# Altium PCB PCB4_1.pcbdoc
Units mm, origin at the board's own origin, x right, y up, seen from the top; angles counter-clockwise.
Board outline 59.69 x 53.72 mm, 2 copper layers (Top Layer, Bottom Layer); 67 components, 68 nets, 256 pads, 103 vias.
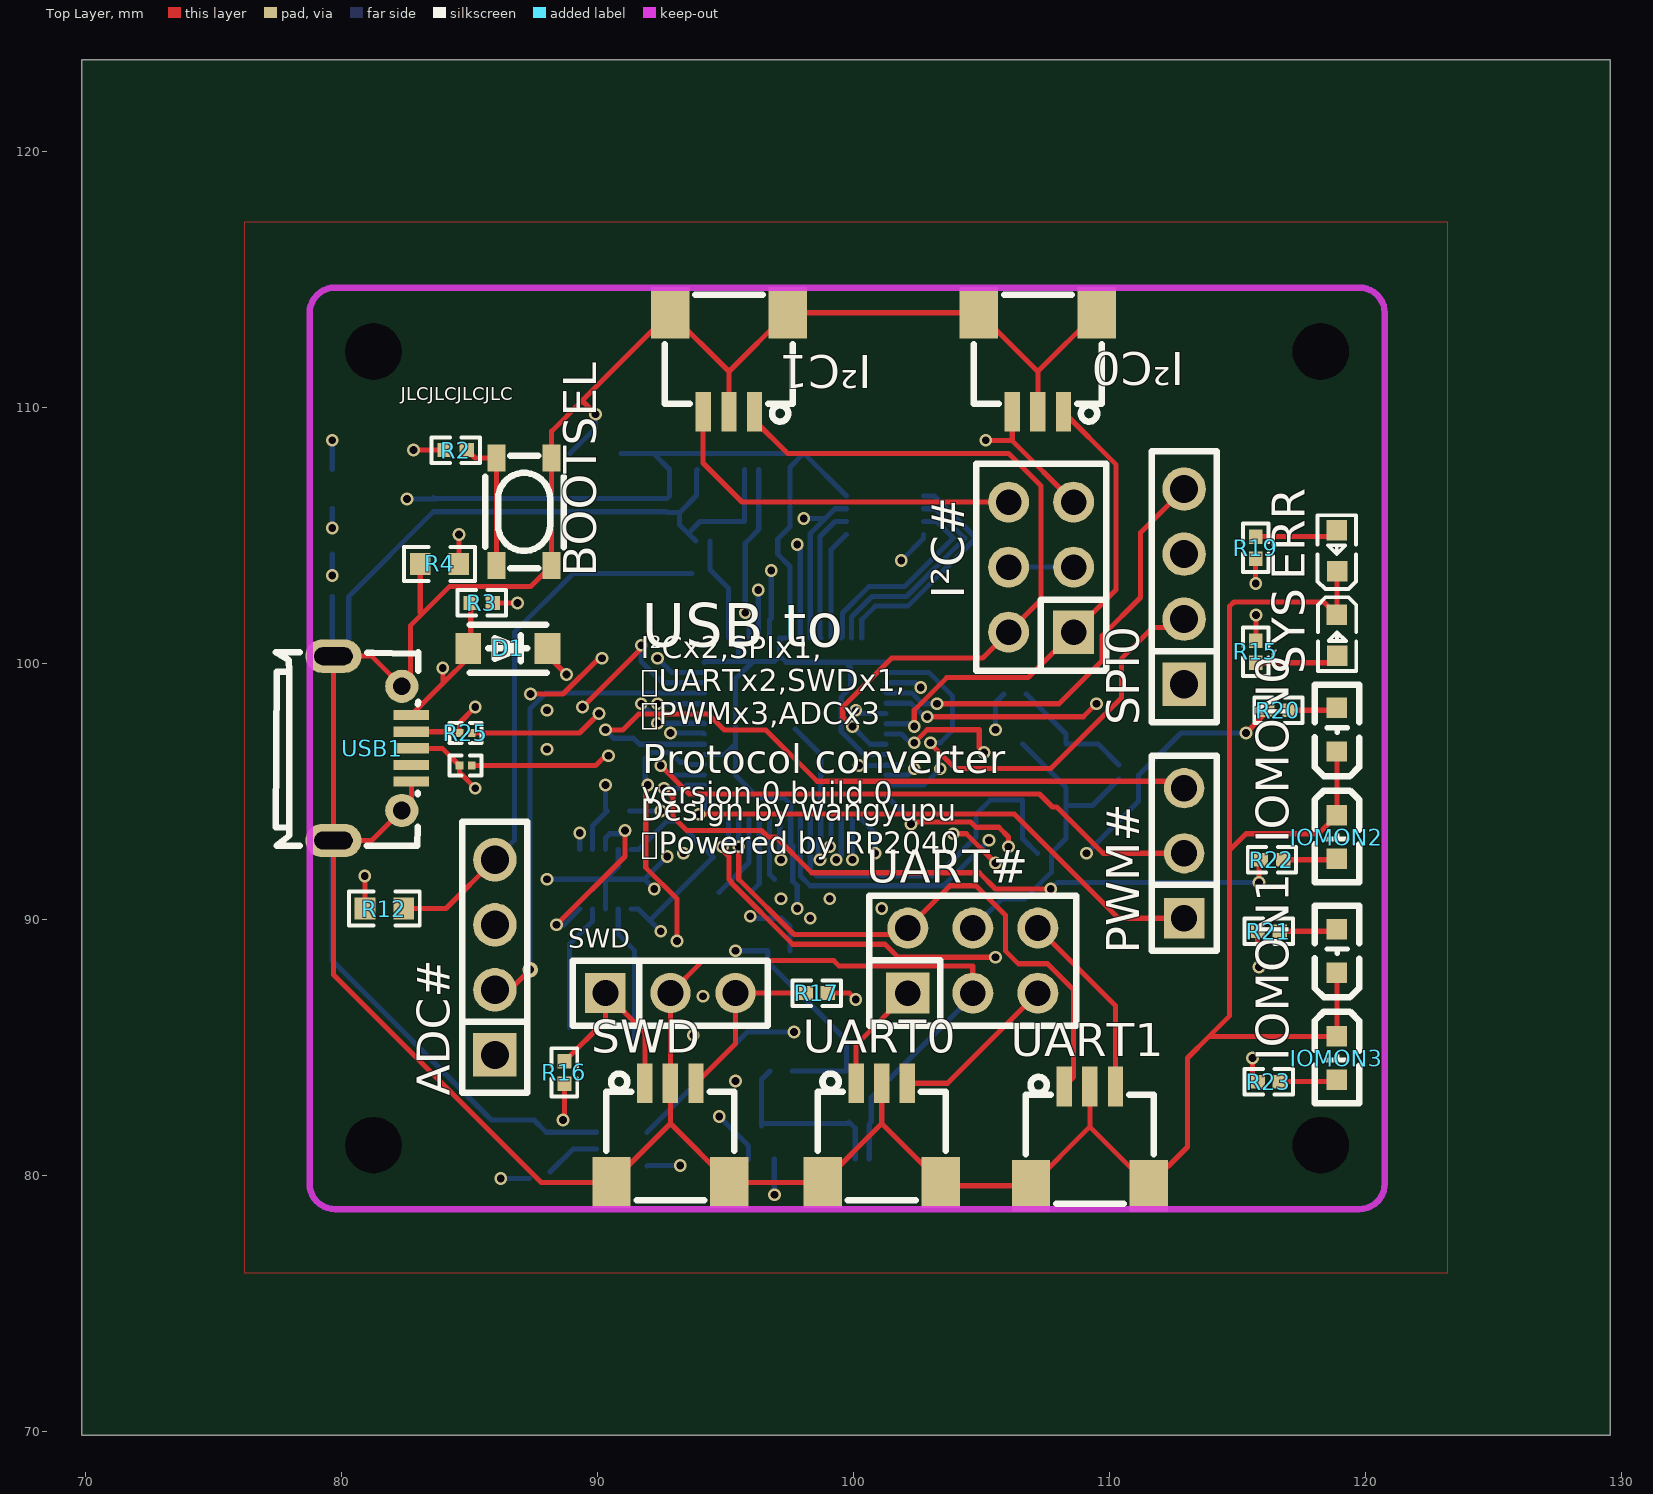
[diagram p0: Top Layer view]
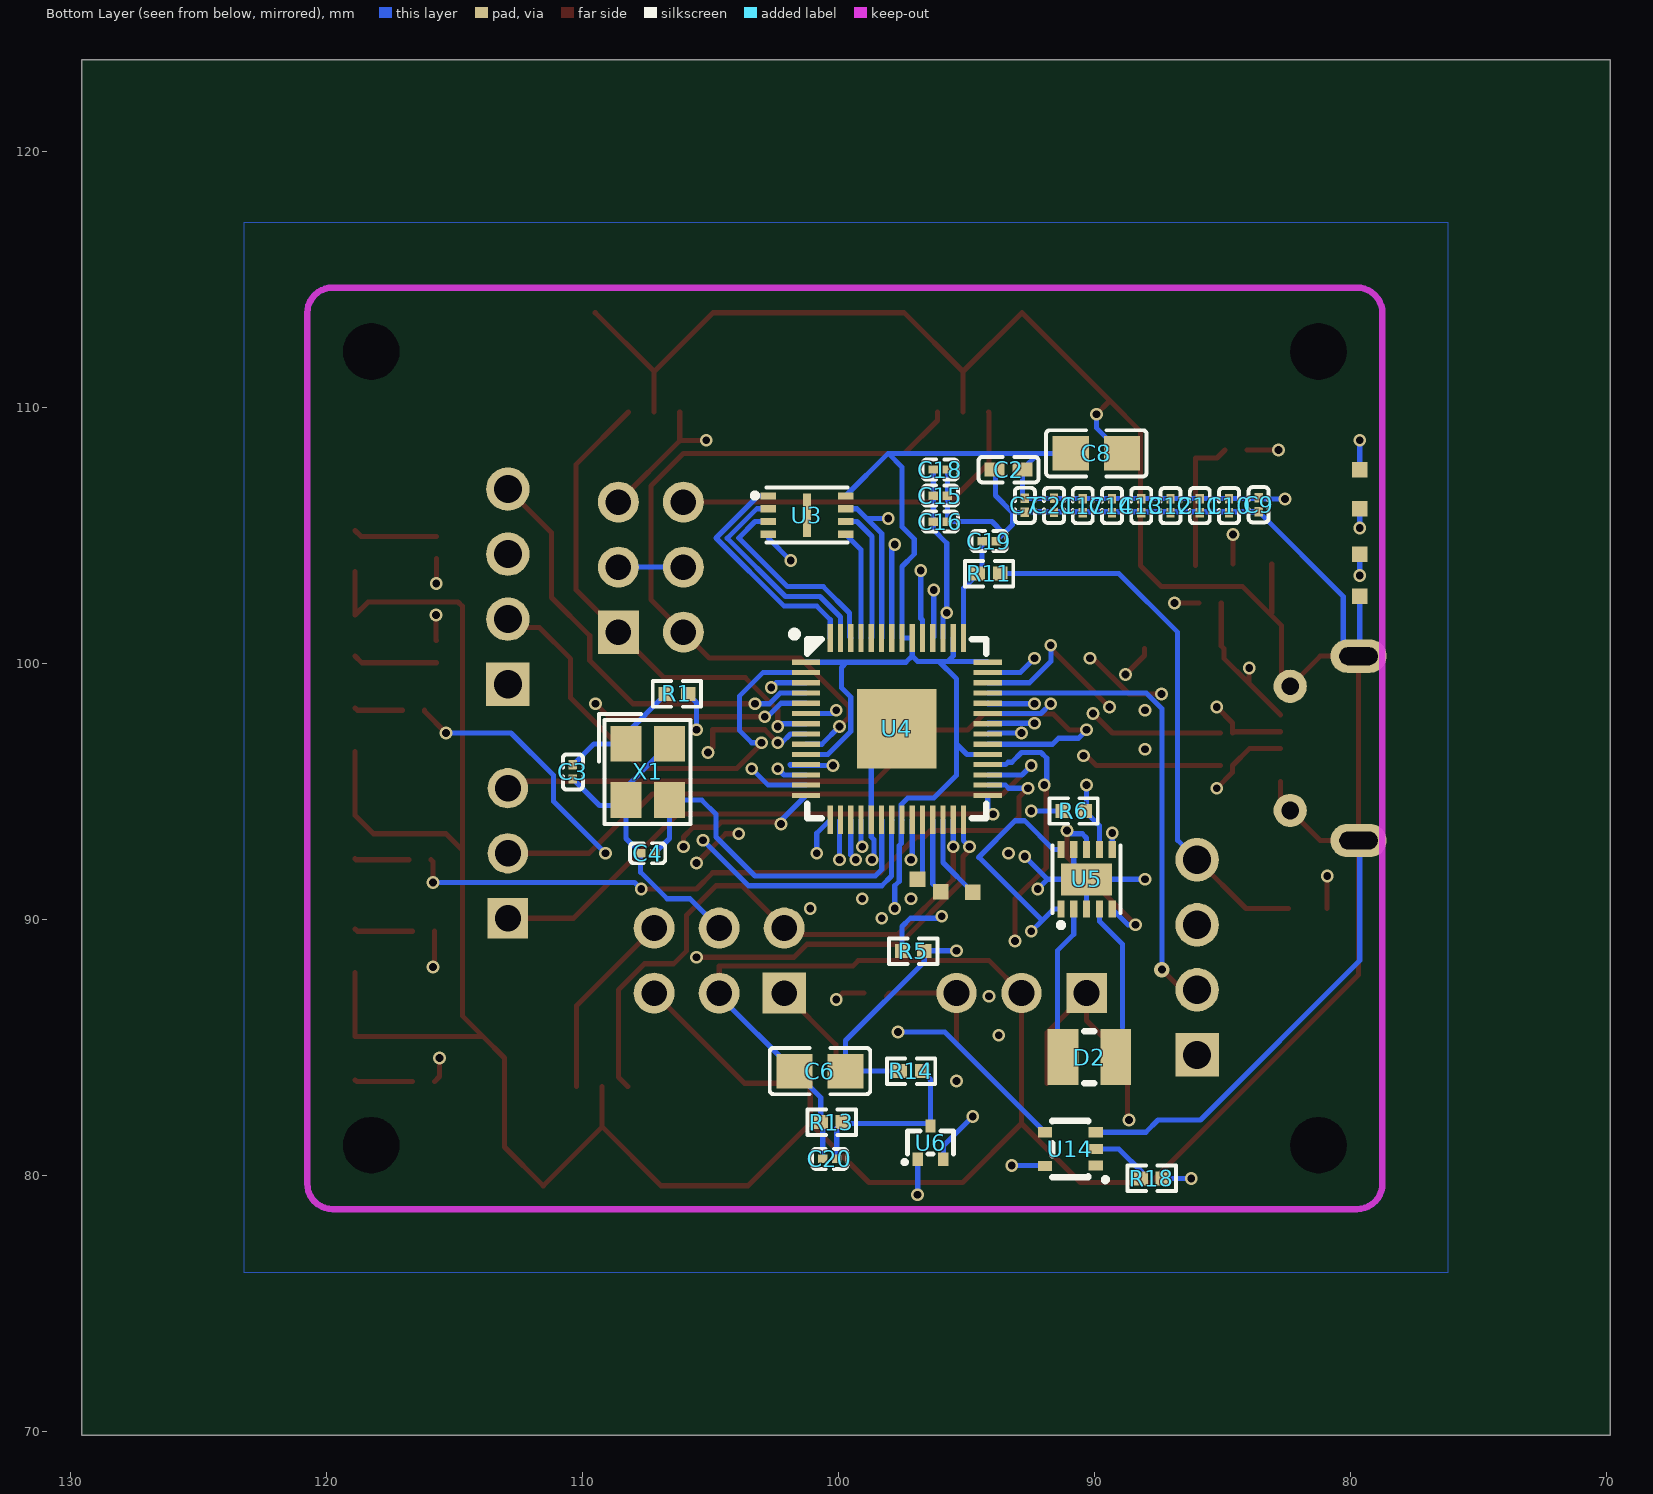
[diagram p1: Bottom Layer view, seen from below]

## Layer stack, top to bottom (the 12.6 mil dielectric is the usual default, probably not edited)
Top Layer: signal copper (thickness not stored)
Dielectric: dielectric 0.32, FR-4, Dk 4.8
Bottom Layer: signal copper (thickness not stored)

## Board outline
129.54,69.85 69.85,69.85 69.85,123.571 129.54,123.571
cut-out: 82.34,112.181 ccw(c81.24,112.181) 80.14,112.181 ccw(c81.24,112.181)
cut-out: 82.34,81.181 ccw(c81.24,81.181) 80.14,81.181 ccw(c81.24,81.181)
cut-out: 119.34,112.181 ccw(c118.24,112.181) 117.14,112.181 ccw(c118.24,112.181)
cut-out: 119.34,81.181 ccw(c118.24,81.181) 117.14,81.181 ccw(c118.24,81.181)

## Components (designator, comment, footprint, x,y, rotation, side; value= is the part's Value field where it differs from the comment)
ADC# "2.54-1*4P母" HDR-TH_4P-P2.54-V-F 85.979,88.519 r90 top
BOOTSEL "SKRPACE010" KEY-SMD_4P-L4.2-W3.2-P2.20-LS4.6 87.122,105.918 r90 top
C2 "CL05A225MQ5NSNC" C0402 93.345,107.569 r0 bottom
C3 "CL03C150JA3ANNC" C0201 110.363,95.758 r90 bottom
C4 "CL03C150JA3ANNC" C0201 107.442,92.583 r180 bottom
C6 "GRM21BR60J476ME01L" C0805 100.711,84.074 r180 bottom
C7 "GRM033R60J104KE19D" C0201 92.71,106.172 r90 bottom
C8 "GRM21BR60J476ME01L" C0805 89.916,108.204 r180 bottom
C9 "GRM033R60J104KE19D" C0201 83.577,106.196 r270 bottom
C10 "GRM033R60J104KE19D" C0201 84.733,106.161 r270 bottom
C11 "GRM033R60J104KE19D" C0201 85.876,106.161 r270 bottom
C12 "GRM033R60J104KE19D" C0201 87.019,106.161 r270 bottom
C13 "GRM033R60J104KE19D" C0201 88.162,106.161 r270 bottom
C14 "GRM033R60J104KE19D" C0201 89.305,106.161 r270 bottom
C15 "GRM033R60J104KE19D" C0201 96.012,106.553 r0 bottom
C16 "GRM033R60J104KE19D" C0201 96.012,105.537 r180 bottom
C17 "GRM033R60J104KE19D" C0201 90.448,106.161 r90 bottom
C18 "GRM033R60J104KE19D" C0201 96.012,107.569 r0 bottom
C19 "GRM033R60J104KE19D" C0201 94.107,104.775 r0 bottom
C20 "GRM033R71E102KA01D" C0201 100.33,80.645 r180 bottom
C21 "GRM033R60J104KE19D" C0201 91.567,106.172 r270 bottom
D1 "MBR120VLSFT1G" SOD-123F_L2.8-W1.8-LS3.7-RD 86.487,100.584 r180 top
D2 "SRN2512-2R2M" IND-SMD_L2.5-W2.0 90.189,84.622 r180 bottom
ERR "NCD0603R1_C84263" LED0603-RD_RED 118.872,104.394 r90 top
IOMON0 "SZYY0603Y" LED0603-R-RD_YELLOW 118.872,97.409 r90 top
IOMON1 "SZYY0603Y" LED0603-R-RD_YELLOW 118.872,88.773 r90 top
IOMON2 "SZYY0603Y" LED0603-R-RD_YELLOW 118.872,93.218 r270 top
IOMON3 "SZYY0603Y" LED0603-R-RD_YELLOW 118.872,84.582 r270 top
I²C0 "SM03B-SRSS-TB(LF)(SN)" CONN-SMD_SM03B-SRSS-TB-LF-SN-P 107.188,111.76 r180 top
I²C1 "SM03B-SRSS-TB(LF)(SN)" CONN-SMD_SM03B-SRSS-TB-LF-SN-P 95.123,111.76 r180 top
I²C# "DS1023-2*3SF11" HDR-TH_6P-P2.54-V-F-R2-C3-S2.54 107.315,103.759 r90 top
PWM# "2.54-1*3P母" HDR-TH_3P-P2.54-V-F 112.903,92.583 r90 top
R1 "AECR0402F1K00K9" R0402 106.299,98.806 r180 bottom
R2 "AECR0402F1K00K9" R0402 84.455,108.331 r0 top
R3 "CR0402F5K60Q10Z" R0402 85.471,102.362 r180 top
R4 "0603WAF1002T5E" R0603 83.82,103.886 r180 top
R5 "RC0402FR-07100KL" R0402 97.072,88.76 r180 bottom
R6 "RC0402FR-07100KL" R0402 90.805,94.234 r180 bottom
R11 "RC0402FR-071RL" R0402 94.107,103.505 r0 bottom
R12 "RC0603FR-07200RL" R0603 81.661,90.424 r0 top
R13 "RC0402FR-07100KL" R0402 100.248,82.08 r180 bottom
R14 "RC0402FR-07200KL" R0402 97.155,84.074 r0 bottom
R15 "RC0402FR-07470RL" R0402 115.697,100.457 r270 top
R16 "CR0402F100RQ10Z" R0402 88.698,84.022 r90 top
R17 "CR0402F100RQ10Z" R0402 98.552,87.122 r180 top
R18 "CR0402F100RQ10Z" R0402 87.757,79.883 r0 bottom
R19 "RC0402FR-07470RL" R0402 115.697,104.521 r90 top
R20 "RC0402FR-07470RL" R0402 116.586,98.171 r0 top
R21 "RC0402FR-07470RL" R0402 116.205,89.535 r0 top
R22 "RC0402FR-07470RL" R0402 116.332,92.329 r0 top
R23 "RC0402FR-07470RL" R0402 116.206,83.661 r0 top
R25 "RC0201FR-0727RL" R0201 84.836,97.282 r180 top
SPI0 "2.54-1*4P母" HDR-TH_4P-P2.54-V-F 112.903,102.997 r90 top
SWD "SM03B-SRSS-TB(LF)(SN)" CONN-SMD_SM03B-SRSS-TB-LF-SN-P 92.837,81.661 r0 top
SWD "2.54-1*3P母" HDR-TH_3P-P2.54-V-F 92.837,87.122 r0 top
SYS "19-217/GHC-YR1S2/3T" LED0603-RD 118.872,101.092 r270 top
U3 "W25Q16JVUXIQ" USON-8_L3.0-W2.0-P0.50-BL-EP 101.219,105.791 r270 bottom
U4 "RP2040_C2040" lqfn-56_l7.0-w7.0-p0.4-ep 97.708,97.443 r180 bottom
U5 "RT6150BGQW" WSON-10_L2.5-W2.5-P0.50-BL-EP 90.297,91.567 r180 bottom
U6 "DMG1012T-13" SOT-523-3_L1.6-W0.8-P1.00-LS1.6-BR 96.393,81.28 r270 bottom
U14 "74AUP1T17GWH" TSSOP-5_L2.1-W1.3-P0.65-LS2.2-BR 90.932,81.026 r180 bottom
UART0 "SM03B-SRSS-TB(LF)(SN)" CONN-SMD_SM03B-SRSS-TB-LF-SN-P 101.092,81.661 r0 top
UART1 "SM03B-SRSS-TB(LF)(SN)" CONN-SMD_SM03B-SRSS-TB-LF-SN-P 109.22,81.534 r0 top
UART# "DS1023-2*3SF11" HDR-TH_6P-P2.54-V-F-R2-C3-S2.54 104.648,88.392 r0 top
USB1 "MicroXNJ" MICRO-USB-SMD_MICROXNJ 81.195,96.681 r270 top
X1 "X322512MMB4SI" CRYSTAL-SMD_4P-L3.2-W2.5-BL 107.442,95.758 r270 bottom
? "RC0201FR-0727RL" R0201 84.836,96.012 r180 top

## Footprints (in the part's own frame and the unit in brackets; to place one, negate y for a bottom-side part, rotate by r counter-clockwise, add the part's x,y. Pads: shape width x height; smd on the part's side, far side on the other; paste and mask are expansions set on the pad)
C0201 [mm]
  rect 0.368x0.324 smd paste-100 mask+0.051: 1(-0.274,0) 2(0.274,0)
  silkscreen extent -0.69,-0.39 0.69,0.39
C0402 [mm]
  rect 0.79x0.54 smd paste-100 mask+0.051: 1(-0.545,0) 2(0.545,0)
  silkscreen extent -1.17,-0.5 1.17,0.5
C0805 [mm]
  rect 1.41x1.35 smd paste-100 mask+0.051: 1(-1,0) 2(1,0)
  silkscreen extent -1.96,-0.9 1.96,0.9
CONN-SMD_SM03B-SRSS-TB-LF-SN-P [mm]
  rect 0.6x1.55 smd mask+0.051: 1(-1,1.938) 2(0,1.938) 3(1,1.938)
  rect 1.5x2 smd mask+0.051: 4(2.3,-1.938) 5(-2.3,-1.938)
  silkscreen extent -2.5,-2.64 2.5,2.32
CRYSTAL-SMD_4P-L3.2-W2.5-BL [mm]
  rect 1.4x1.2 smd paste+0 mask+0.051: 1(-1.1,-0.85) 2(1.1,-0.85) 3(1.1,0.85) 4(-1.1,0.85)
  silkscreen extent -2.26,-1.91 2.03,1.68
HDR-TH_3P-P2.54-V-F [mil]
  rect 62x62 hole 40.16 mask+2.01: 1(-100,0)
  round 62 hole 40.16 mask+2.01: 2(0,0) 3(100,0)
  silkscreen extent -150,-50 150,50
HDR-TH_4P-P2.54-V-F [mm]
  rect 1.7x1.7 hole 1.1 mask+0.051: 1(-3.81,0)
  round 1.7 hole 1.1 mask+0.051: 2(-1.27,0) 3(1.27,0) 4(3.81,0)
  silkscreen extent -5.29,-1.27 5.29,1.27
HDR-TH_6P-P2.54-V-F-R2-C3-S2.54 [mm]
  rect 1.7x1.6 hole 1 mask+0.051: 1(-2.54,-1.27)
  round 1.6 hole 1 mask+0.051: 2(-2.54,1.27) 3(0,-1.27) 4(0,1.27) 5(2.54,-1.27) 6(2.54,1.27)
  silkscreen extent -4.04,-2.54 4.04,2.54
IND-SMD_L2.5-W2.0 [mm]
  rect 1.2x2.2 smd paste+0 mask+0.051: 1(1.028,0) 2(-1.028,0)
  silkscreen extent -0.2,-1.02 0.2,1.02
KEY-SMD_4P-L4.2-W3.2-P2.20-LS4.6 [mm]
  rect 1.05x0.7 smd mask+0.051: 1(-2.1,1.075) 2(2.1,1.075) 3(-2.1,-1.075) 4(2.1,-1.075)
  silkscreen extent -2.2,-1.55 2.2,1.52
LED0603-R-RD_YELLOW [mm]
  rect 0.8x0.8 smd mask+0.051: 1(0.851,0) 2(-0.851,0)
  silkscreen extent -1.82,-0.86 1.77,0.86
LED0603-RD [mm]
  rect 0.8x0.8 smd paste+0 mask+0.051: 1(-0.799,-0.003) 2(0.799,0.003)
  silkscreen extent -1.49,-0.75 1.39,0.76
LED0603-RD_RED [mm]
  rect 0.8x0.8 smd mask+0.051: 1(-0.8,-0.003) 2(0.8,0.003)
  silkscreen extent -1.49,-0.75 1.39,0.76
lqfn-56_l7.0-w7.0-p0.4-ep [mm]
  rect 1.1x0.2 smd paste-100 mask+0.05: 1(-3.55,2.6) 2(-3.55,2.2) 3(-3.55,1.8) 4(-3.55,1.4) 5(-3.55,1) 6(-3.55,0.6) 7(-3.55,0.2) 8(-3.55,-0.2) 9(-3.55,-0.6) 10(-3.55,-1) 11(-3.55,-1.4) 12(-3.55,-1.8) 13(-3.55,-2.2) 14(-3.55,-2.6) 29(3.55,-2.6) 30(3.55,-2.2) 31(3.55,-1.8) 32(3.55,-1.4) 33(3.55,-1) 34(3.55,-0.6) 35(3.55,-0.2) 36(3.55,0.2) 37(3.55,0.6) 38(3.55,1) 39(3.55,1.4) 40(3.55,1.8) 41(3.55,2.2) 42(3.55,2.6)
  rect 0.2x1.1 smd paste-100 mask+0.05: 15(-2.6,-3.55) 16(-2.2,-3.55) 17(-1.8,-3.55) 18(-1.4,-3.55) 19(-1,-3.55) 20(-0.6,-3.55) 21(-0.2,-3.55) 22(0.2,-3.55) 23(0.6,-3.55) 24(1,-3.55) 25(1.4,-3.55) 26(1.8,-3.55) 27(2.2,-3.55) 28(2.6,-3.55) 43(2.6,3.55) 44(2.2,3.55) 45(1.8,3.55) 46(1.4,3.55) 47(1,3.55) 48(0.6,3.55) 49(0.2,3.55) 50(-0.2,3.55) 51(-0.6,3.55) 52(-1,3.55) 53(-1.4,3.55) 54(-1.8,3.55) 55(-2.2,3.55) 56(-2.6,3.55)
  rect 3.1x3.1 smd paste-100 mask+0.05: 57(0,0)
  silkscreen extent -4.13,-3.5 3.5,3.83
MICRO-USB-SMD_MICROXNJ [mm]
  rect 0.4x1.4 smd paste-100 mask+0.051: 1(-1.3,1.521) 2(-0.65,1.521) 3(0,1.521) 4(0.65,1.521) 5(1.3,1.521)
  round 1.3 hole 0.7 mask+0.051: 6(2.425,1.149) 9(-2.425,1.149)
  oval 1.3x2.2 hole 0.7 slot 1.5 at 90 deg mask+0.051: 7(3.6,-1.521) 8(-3.6,-1.521)
  silkscreen extent -3.76,-3.78 3.8,1.79
R0201 [mm]
  rect 0.303x0.324 smd paste-100 mask+0.051: 1(-0.242,0) 2(0.242,0)
  silkscreen extent -0.62,-0.39 0.62,0.39
R0402 [mm]
  rect 0.566x0.54 smd paste-100 mask+0.051: 1(-0.433,0) 2(0.433,0)
  silkscreen extent -0.94,-0.5 0.94,0.5
R0603 [mm]
  rect 0.806x0.864 smd paste-100 mask+0.051: 1(-0.753,0) 2(0.753,0)
  silkscreen extent -1.39,-0.66 1.39,0.66
SOD-123F_L2.8-W1.8-LS3.7-RD [mm]
  rect 1x1.2 smd paste+0 mask+0.051: 1(-1.55,0) 2(1.55,0)
  silkscreen extent -1.52,-0.93 1.49,0.95
SOT-523-3_L1.6-W0.8-P1.00-LS1.6-BR [mm]
  rect 0.51x0.4 smd paste+0 mask+0.051: 1(0.65,-0.5) 2(0.65,0.5) 3(-0.65,0)
  silkscreen extent -0.45,-1.08 0.83,0.9
TSSOP-5_L2.1-W1.3-P0.65-LS2.2-BR [mil]
  rect 21.7x15.7 smd paste+0 mask+1.97: 1(39,-25) 2(39,0) 3(39,26) 4(-39,26) 5(-39,-26)
  silkscreen extent -28,-49 56,43
USON-8_L3.0-W2.0-P0.50-BL-EP [mm]
  rect 0.28x0.6 smd paste+0 mask+0.051: 1(-0.75,-1.507) 2(-0.25,-1.507) 3(0.25,-1.507) 4(0.75,-1.507) 5(0.75,1.507) 6(0.25,1.507) 7(-0.25,1.507) 8(-0.75,1.507)
  rect 1.7x0.3 smd paste+0 mask+0.051: 9(0,0)
  silkscreen extent -1.08,-2.13 1.08,1.58
WSON-10_L2.5-W2.5-P0.50-BL-EP [mm]
  rect 0.28x0.665 smd paste+0 mask+0.051: 1(-1,-1.157) 2(-0.5,-1.157) 3(0,-1.157) 4(0.5,-1.157) 5(1,-1.157) 6(1,1.157) 7(0.5,1.157) 8(0,1.157) 9(-0.5,1.157) 10(-1,1.157)
  rect 2x1.25 smd paste+0 mask+0.051: 11(0,0)
  silkscreen extent -1.33,-1.89 1.33,1.33

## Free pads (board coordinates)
  rect 0.61x0.61 smd far side mask+0.051: TP1(79.629,102.616) TP1(94.742,91.059) TP1(95.994,91.077) TP1(96.901,91.567) TP2(79.629,107.569) TP3(79.629,106.045) TP4(79.629,104.267)

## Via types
v1: diameter 0.5, hole 0.305, Top Layer to Bottom Layer, 102 vias
v2: diameter 0.61, hole 0.305, Top Layer to Bottom Layer, 1 vias

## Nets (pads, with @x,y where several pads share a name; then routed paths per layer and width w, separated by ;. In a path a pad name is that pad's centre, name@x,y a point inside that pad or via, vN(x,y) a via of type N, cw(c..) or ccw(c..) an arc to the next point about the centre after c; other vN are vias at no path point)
0ADC0: ADC#.1 U4.38 | length 24
  Top Layer w0.2: v1(87.376,98.806) 88.646,98.806 90.043,100.203 v1(90.17,100.203)
  Inner1 w0.2: v1(87.376,98.806) 87.376,98.679 87.122,98.425 88.011,97.536 v1(88.011,96.647) ; v1(90.17,100.203) 90.805,100.203 92.329,98.679 v1(92.329,98.425)
  Inner2 w0.2: ADC#.1 88.011,86.741 88.011,88.392 87.811,88.592 87.811,90.732 88.471,91.392 88.471,92.075 88.011,92.535 v1(88.011,96.647)
  Bottom Layer w0.2: 92.583,98.425 94.14,98.425 U4.38
0ADC1: ADC#.2 U4.39 | length 19
  Top Layer w0.2: ADC#.2 86.568,87.249 v2(87.356,88.037)
  Bottom Layer w0.2: v2(87.356,88.037) 87.356,98.231 87.968,98.843 U4.39
0ADC2: ADC#.3 U4.40 | length 17.5
  Top Layer w0.2: v1(89.408,98.298) 91.694,100.584 v1(91.694,100.711)
  Inner1 w0.2: v1(88.011,98.171) 88.138,98.298 v1(89.408,98.298)
  Inner2 w0.2: ADC#.3 87.376,91.186 87.376,97.536 v1(88.011,98.171)
  Bottom Layer w0.2: v1(91.694,100.711) 91.694,100.076 92.527,99.243 U4.40
0CPU-U: R15.1 U4.37 | length 40.6
  Top Layer w0.2: R15.1 115.708,100.901 v1(115.708,101.891)
  Inner2 w0.2: v1(91.694,98.425) 91.694,92.583 92.456,91.821 102.997,91.821 104.521,93.345 104.521,97.79 105.664,98.933 109.347,98.933 110.871,100.457 114.274,100.457 v1(115.708,101.891)
  Bottom Layer w0.2: v1(91.694,98.425) 92.075,98.044 U4.37
0GP10: R19.1 U4.13 | length 21.3
  Top Layer w0.2: v1(115.697,103.119) R19.1
  Inner2 w0.2: v1(103.378,95.885) 104.219,96.726 104.219,97.915 104.521,98.217 104.521,101.473 105.41,102.362 109.347,102.362 110.104,103.119 v1(115.697,103.119)
  Bottom Layer w0.2: U4.13 102.736,95.243 v1(103.378,95.885)
0GP11: R20.1 U4.14 | length 19.1
  Top Layer w0.2: v1(102.235,93.726) 102.317,93.808 104.566,93.808 104.775,93.599 105.664,93.599 106.045,93.218 v1(106.045,92.837) ; v1(115.316,97.282) 116.153,98.119 R20.1
  Inner2 w0.2: v1(106.045,92.837) 108.839,92.837 v1(109.093,92.583)
  Bottom Layer w0.2: U4.14 102.235,93.866 v1(102.235,93.726) ; v1(109.093,92.583) 111.125,94.615 111.125,95.631 112.776,97.282 v1(115.316,97.282)
0GP15: R21.1 U4.18 | length 21.6
  Top Layer w0.2: v1(103.886,93.345) 104.394,93.345 v1(105.537,92.202) ; R21.1 115.772,88.19 v1(115.824,88.138)
  Inner2 w0.2: v1(99.06,92.837) 99.568,93.345 v1(103.886,93.345) ; v1(105.537,92.202) 107.442,92.202 111.506,88.138 v1(115.824,88.138)
  Bottom Layer w0.2: v1(99.06,92.837) 99.108,92.885 U4.18
0GP19: R22.1 U4.30 | length 28
  Top Layer w0.2: v1(92.583,95.123) 92.933,94.773 92.933,94.011 93.472,93.472 96.393,93.472 96.647,93.218 96.961,93.218 98.358,91.821 104.902,91.821 105.537,91.186 v1(107.696,91.186) ; v1(115.824,91.44) 115.824,92.254 R22.1
  Bottom Layer w0.2: v1(92.583,95.123) 93.338,95.123 93.458,95.243 U4.30 ; v1(107.696,91.186) 107.95,91.44 v1(115.824,91.44)
0GP21: R23.1 U4.32 | length 39.9
  Top Layer w0.2: v1(91.948,95.25) 91.875,95.177 91.875,92.021 93.091,90.805 v1(93.091,89.154) ; v1(115.57,84.582) 115.57,83.864 R23.1
  Inner1 w0.2: v1(93.091,89.154) 92.583,88.646 91.948,88.646 91.59,88.288 91.59,86.21 93.218,84.582 v1(115.57,84.582)
  Bottom Layer w0.2: v1(91.948,95.25) 91.852,95.346 91.852,96.297 92.075,96.52 92.837,96.52 93.218,96.139 93.362,96.139 93.458,96.043 U4.32
0GPIO23: R6.2 U4.35 U5.7 | length 7.5
  Inner1 w0.2: v1(90.297,95.25) 90.424,95.25 92.456,97.282 v1(92.837,97.282)
  Bottom Layer w0.2: U5.7 89.797,93.659 R6.2 90.297,94.309 v1(90.297,95.25) ; v1(92.837,97.282) 94.119,97.282 U4.35
0GPIO24: R3.1 R4.1 U4.36 | length 15.4
  Top Layer w0.2: R4.1 84.573,105.02 v1(84.582,105.029) ; R3.1 v1(86.868,102.362)
  Inner1 w0.2: v1(84.582,105.029) 86.868,102.743 v1(86.868,102.362) 91.767,97.463 92.129,97.463 v1(92.329,97.663) 92.583,97.663
  Bottom Layer w0.2: v1(92.329,97.663) 94.138,97.663 U4.36
0USB0: ?.1 U4.47 | length 21.1
  Top Layer w0.2: ?.1 89.916,96.012 90.297,96.393 v1(90.424,96.393)
  Inner2 w0.2: v1(90.424,96.393) 90.482,96.393 91.205,97.116 91.205,101.746 91.948,102.489 95.885,102.489 96.231,102.143 96.742,102.653 96.742,103.6 v1(96.774,103.632)
  Bottom Layer w0.2: U4.47 96.708,101.693 96.774,101.759 v1(96.774,103.632)
0USB1: R25.1 U4.46 | length 17.7
  Top Layer w0.2: R25.1 89.281,97.282 v1(90.043,98.044)
  Inner2 w0.2: v1(90.043,98.044) 90.805,98.044 90.805,102.008 91.667,102.87 v1(96.266,102.87)
  Bottom Layer w0.2: v1(96.266,102.87) 96.266,101.035 U4.46
1V10: C15.2 C16.1 C18.2 U4.23 U4.45 U4.50 | length 27.8
  Inner2 w0.2: v1(95.758,101.981) 95.966,101.981 96.231,101.716 97.917,103.401 ; v1(97.155,92.329) 97.155,92.964 97.917,93.726 97.917,103.401 ; v1(97.79,104.648) 97.79,103.528 97.917,103.401
  Bottom Layer w0.2: U4.45 95.908,101.831 v1(95.758,101.981) 95.758,104.696 96.286,105.224 C16.1 C15.2 C18.2 ; U4.23 97.108,92.376 v1(97.155,92.329) ; v1(97.79,104.648) 97.908,104.53 U4.50
12: R16.1 U4.15 | length 23.5
  Top Layer w0.2: v1(88.646,82.169) 88.698,82.221 R16.1
  Inner1 w0.2: v1(93.726,85.471) 95.758,85.471 96.901,86.614 96.901,88.646 v1(98.298,90.043) ; v1(100.838,92.583) 101.092,92.329 v1(101.092,90.424)
  Inner2 w0.2: v1(88.646,82.169) 91.948,85.471 v1(93.726,85.471) ; v1(98.298,90.043) 98.552,90.297 98.552,91.186 98.679,91.313 100.203,91.313 v1(101.092,90.424)
  Bottom Layer w0.2: U4.15 100.838,93.363 v1(100.838,92.583)
13: U4.16 U14.4 | length 16.6
  Inner1 w0.2: v1(97.663,85.598) 99.949,87.884 v1(99.949,92.329)
  Bottom Layer w0.2: U14.4 95.834,85.598 v1(97.663,85.598) ; U4.16 99.949,93.852 v1(99.949,92.329)
14: R17.1 U4.17 | length 9.1
  Top Layer w0.2: R17.1 99.822,87.122 v1(100.076,86.868)
  Inner1 w0.2: v1(99.06,90.805) 99.314,91.059 v1(99.314,92.329)
  Inner2 w0.2: v1(99.06,90.805) 99.568,90.805 100.076,90.297 v1(100.076,86.868)
  Bottom Layer w0.2: v1(99.314,92.329) 99.508,92.523 U4.17
24: pad.TP1@96.901,91.567 U4.24 | length 2.4
  Bottom Layer w0.2: U4.24 96.708,91.76 pad.TP1@96.901,91.567
25: pad.TP1@95.994,91.077 U4.25 | length 2.9
  Bottom Layer w0.2: pad.TP1@95.994,91.077 96.308,91.391 U4.25
26: pad.TP1@94.742,91.059 U4.26 | length 3.3
  Bottom Layer w0.2: pad.TP1@94.742,91.059 95.908,92.225 U4.26
$1N2647: R5.1 U5.6 | length 11.3
  Inner1 w0.2: v1(89.297,93.378) 92.553,90.121 v1(95.956,90.121)
  Bottom Layer w0.2: U5.6 v1(89.297,93.378) ; v1(95.956,90.121) 96.035,90.043 97.183,90.043 97.505,89.721 R5.1
$1N2652: D2.1 U5.4 | length 5
  Bottom Layer w0.2: 88.9,85.772 88.9,89.029 89.797,89.926 U5.4
$1N2653: D2.2 U5.2 | length 5.4
  Bottom Layer w0.2: U5.2 90.797,89.416 91.44,88.773 D2.2@91.44,85.288
$1N2691: C3.2 R1.1 X1.1 | length 5
  Bottom Layer w0.2: R1.1 108.292,97.246 X1.1 109.537,96.858 C3.2
$1N2815: U4.41 U6.2 | length 26.9
  Inner1 w0.2: v1(93.345,92.583) 93.98,92.583 94.742,91.821 94.942,91.821 96.767,89.996 96.767,89.798 96.63,89.662 95.123,89.662 94.107,88.646 v1(94.107,86.995)
  Inner2 w0.2: v1(92.329,100.203) 92.329,99.441 92.71,99.441 93.345,98.806 v1(93.345,92.583) ; v1(94.107,86.995) 94.107,86.487 94.742,85.852 v1(94.742,82.296)
  Bottom Layer w0.2: v1(92.329,100.203) 92.889,99.643 U4.41 ; v1(94.742,82.296) 95.893,81.145 U6.2
$1N2838: C20.2 R13.2 R14.1 U6.3 | length 7.3
  Bottom Layer w0.2: U6.3 U6.3@96.393,82.034 ; R14.1 96.393,83.745 U6.3@96.393,82.034 ; C20.2 100.056,81.84 R13.2 99.769,82.034 U6.3@96.393,82.034
$1N4030: BOOTSEL.1 BOOTSEL.2 R2.2 | length 5.5
  Top Layer w0.2: R2.2 85.201,108.018 BOOTSEL.2 BOOTSEL.1
$1N4773: R18.2 U14.2 | length 2.2
  Bottom Layer w0.2: R18.2@88.138,80.137 89.027,81.026 U14.2
$1N4884: R15.2 SYS.2 | length 3.3
  Top Layer w0.2: R15.2 118.607,100.024 SYS.2
$1N5172: ERR.2 R19.2 | length 3.3
  Top Layer w0.2: R19.2 118.629,104.954 ERR.2
$1N5459: IOMON0.1 R20.2 | length 1.9
  Top Layer w0.2: R20.2 118.783,98.171 IOMON0.1
$1N5495: IOMON1.1 R21.2 | length 2.3
  Top Layer w0.2: R21.2 118.783,89.535 IOMON1.1
$1N5531: IOMON2.1 R22.2 | length 2.1
  Top Layer w0.2: R22.2 118.834,92.329 IOMON2.1
$1N5567: IOMON3.1 R23.2 | length 2.3
  Top Layer w0.2: R23.2 118.802,83.661 IOMON3.1
$1N5599: C19.2 R11.2 U4.43 | length 4.1
  Bottom Layer w0.2: C19.2 94.381,103.663 R11.2 95.108,102.937 U4.43
$1N5775: pad.TP3 R25.2 USB1.2 | length 13.5
  Top Layer w0.2: USB1.2 84.545,97.331 R25.2 84.594,97.675 v1(85.217,98.298)
  Inner2 w0.2: v1(79.629,105.283) 83.439,101.473 83.439,99.576 83.828,99.187 84.328,99.187 v1(85.217,98.298)
  Bottom Layer w0.2: v1(79.629,105.283) pad.TP3
$1N5777: ?.2 pad.TP4 USB1.3 | length 15.1
  Top Layer w0.2: USB1.3 83.925,96.681 ?.2 84.594,95.746 v1(85.217,95.123)
  Inner2 w0.2: v1(79.629,103.433) 81.153,101.909 81.153,98.552 84.582,95.123 v1(85.217,95.123)
  Bottom Layer w0.2: v1(79.629,103.433) pad.TP4
$1N5998: C6.2 D1.1 R5.2 R14.2 U5.5 U5.8 | length 38.8
  Top Layer w0.2: D1.1 88.037,100.304 v1(88.773,99.568) ; v1(88.392,89.789) 91.059,92.456 v1(91.059,93.472)
  Inner2 w0.2: v1(88.773,99.568) 88.773,90.17 ; v1(91.059,93.472) 91.059,92.456 88.773,90.17 ; v1(95.377,88.773) 90.17,88.773 88.773,90.17
  Bottom Layer w0.2: v1(88.392,89.789) 88.676,89.789 U5.5 ; U5.8 90.297,93.176 90.466,93.345 90.932,93.345 v1(91.059,93.472) ; v1(95.377,88.773) 96.626,88.773 R5.2 96.64,88.339 99.711,85.268 C6.2 R14.2
ADC_VERF: ADC#.4 R11.1 R12.2 | length 21.4
  Top Layer w0.2: R12.2 84.074,90.424 ADC#.4
  Bottom Layer w0.2: ADC#.4 86.741,93.091 86.741,101.219 89.027,103.505 R11.1
AVCC: D1.2 pad.TP2 R3.2 USB1.1 | length 17.8
  Top Layer w0.2: USB1.1 83.975,99.24 ; v1(83.947,99.822) 83.947,99.269 83.975,99.24 ; R3.2 85.038,100.685 D1.2 84.937,100.202 83.975,99.24
  Inner2 w0.2: v1(79.629,108.712) 83.947,104.394 v1(83.947,99.822)
  Bottom Layer w0.2: pad.TP2 v1(79.629,108.712)
BOOTSEL_TO_EEPROM: R2.1 U3.7 U4.51 | length 24.3
  Top Layer w0.2: v1(82.804,108.331) R2.1
  Inner2 w0.2: v1(82.804,108.331) 95.377,108.331 v1(98.044,105.664)
  Bottom Layer w0.2: v1(98.044,105.664) 98.884,105.664 ; U4.51 98.298,101.003 98.298,105.078 98.884,105.664 ; U3.7 99.261,106.041 98.884,105.664
EPCLK0: U3.6 U4.52 | length 5.3
  Bottom Layer w0.2: U4.52 98.679,101.022 98.679,104.959 99.261,105.541 U3.6
EPSD00: U3.5 U4.53 | length 4.3
  Bottom Layer w0.2: U4.53 99.108,104.437 U3.5
EPSD10: U3.2 U4.55 | length 8.6
  Bottom Layer w0.2: U4.55 99.908,101.813 100.711,102.616 102.062,102.616 104.332,104.886 103.177,106.041 U3.2
EPSD20: U3.3 U4.54 | length 8
  Bottom Layer w0.2: U4.54 99.556,101.041 99.556,101.969 100.584,102.997 101.981,102.997 103.886,104.902 103.247,105.541 U3.3
EPSS0: U3.1 U4.56 | length 9.2
  Bottom Layer w0.2: U4.56 100.308,101.705 100.838,102.235 102.108,102.235 104.775,104.902 103.136,106.541 U3.1
GND: BOOTSEL.3 BOOTSEL.4 C2.2 C3.1 C4.1 C6.1 C7.1 C8.2 C9.2 C10.2 C11.2 C12.2 C13.2 C14.2 C15.1 C16.2 C17.1 C18.1 C19.1 C20.1 C21.2 ERR.1 IOMON0.2 IOMON1.2 IOMON2.2 IOMON3.2 I²C0.2 I²C0.4 I²C0.5 I²C1.2 I²C1.4 I²C1.5 I²C#.3 I²C#.4 pad.TP1@79.629,102.616 R4.2 R6.1 R13.1 SWD.2 SWD.4 SWD.5 SYS.1 U3.4 U4.19 U4.57 U5.3 U5.9 U5.11 U14.3 UART0.2 UART0.4 UART0.5 UART1.2 UART1.4 UART1.5 UART#.3 UART#.4 USB1.5 USB1.6 USB1.7 USB1.8 USB1.9 X1.2 X1.4 | length 299.8
  Top Layer w0.2: USB1.5 82.716,94.629 USB1.6 81.169,93.081 USB1.7 ; R4.2 83.067,101.98 83.125,101.921 ; v1(89.916,109.728) 89.417,110.227 89.352,110.227 ; I²C1.2 95.123,111.398 ; SWD.4 UART0.5 101.092,82.023 ; SWD.4 92.837,82.024 ; UART0.2 101.092,82.023 ; UART#.3 104.648,88.174 99.431,88.174 99.218,88.387 94.102,88.387 92.837,87.122 92.837,83.599 92.837,82.024 ; I²C0.2 107.188,111.398 ; UART1.2 109.22,81.896 ; I²C0.5@109.488,113.698 107.188,111.398 ; IOMON1.2 IOMON3.2 113.881,85.433 ; IOMON0.2 IOMON2.2 118.148,93.345 115.316,93.345 114.681,92.71 ; ERR.1 118.875,101.898 SYS.1 118.361,102.399 114.845,102.399 114.681,102.235 114.681,92.71 ; USB1.7 USB1.8 81.169,100.281 USB1.9 82.677,99.439 82.677,101.473 83.125,101.921 ; USB1.7 79.674,87.839 87.79,79.723 SWD.5 92.837,82.024 ; 83.125,101.921 84.201,102.997 87.376,102.997 BOOTSEL.3 BOOTSEL.4 88.197,109.072 89.352,110.227 ; 89.352,110.227 I²C1.4 95.123,111.398 ; 95.123,111.398 I²C1.5 I²C0.4 107.188,111.398 ; 101.092,82.023 UART0.4 103.519,79.596 UART1.5 109.22,81.896 ; 109.22,81.896 UART1.4 113.03,81.106 113.03,84.582 113.881,85.433 ; 113.881,85.433 114.681,86.233 114.681,92.71
  Inner1 w0.2: USB1.6 82.576,94.488 87.122,94.488 88.011,93.599 v1(88.011,91.567) ; v1(92.456,94.234) 92.71,93.98 v1(92.71,92.456) ; v1(97.155,90.805) v1(98.679,92.329) ; UART#.4 104.648,102.362 I²C#.4
  Inner2 w0.2: v1(92.202,91.186) 92.583,90.805 v1(97.155,90.805) ; v1(101.854,104.013) 105.791,104.013 I²C#.4 ; UART#.3 UART#.4
  Bottom Layer w0.2: pad.TP1@79.629,102.616 79.629,100.326 USB1.8 80.271,100.878 80.271,102.616 C9.2 92.686,105.922 C7.1 93.198,105.898 ; USB1.7 79.629,93.036 79.629,88.392 85.852,82.169 87.503,82.169 87.986,81.686 U14.3 ; v1(88.011,91.567) U5.11 ; C8.2 89.916,109.204 v1(89.916,109.728) ; U5.3 U5.11 ; U5.9 90.797,92.067 U5.11 ; R6.1 v1(92.456,94.234) ; v1(92.202,91.186) 91.821,91.567 ; v1(92.71,92.456) 91.821,91.567 ; C19.1 93.53,105.077 ; C2.2 93.853,107.532 93.853,106.553 93.198,105.898 ; C18.1 C15.1 C16.2 93.99,105.537 93.53,105.077 ; U4.57 98.708,96.443 U4.19 98.708,93.218 98.6,93.11 98.6,92.408 v1(98.679,92.329) ; C20.1 100.604,82.003 R13.1 100.681,83.044 C6.1 104.648,87.011 UART#.3 ; v1(101.854,104.013) 102.726,104.885 U3.4 ; UART#.4 105.791,90.805 106.68,90.805 107.716,91.841 C4.1 108.292,93.159 X1.2@108.292,94.448 ; I²C#.4 I²C#.3 ; X1.4 108.292,95.158 X1.2 X1.2@108.292,94.448 ; C3.1 109.327,94.448 X1.2@108.292,94.448 ; U5.11 91.821,91.567 ; 93.198,105.898 93.198,105.41 93.53,105.077
I0C: I²C0.1 I²C#.1 U4.7 | length 19.4
  Top Layer w0.2: v1(102.362,97.536) 102.362,98.171 103.632,99.441 106.807,99.441 I²C#.1 110.236,102.87 110.236,107.775 I²C0.1
  Bottom Layer w0.2: U4.7 102.255,97.643 v1(102.362,97.536)
I0D: I²C0.3 I²C#.5 U4.6 | length 19.4
  Top Layer w0.2: v1(105.156,108.712) 106.172,108.712 106.188,108.696 ; I²C0.3 106.188,108.696 ; I²C#.5 106.188,108.696
  Inner1 w0.2: v1(100.076,98.171) 101.6,99.695 101.6,100.965 104.521,103.886 104.521,108.077 v1(105.156,108.712)
  Bottom Layer w0.2: v1(100.076,98.171) 100.204,98.043 U4.6
I1C: I²C1.1 I²C#.2 U4.9 | length 29
  Top Layer w0.2: I²C1.1 96.123,109.49 97.409,108.204 106.045,108.204 107.315,106.934 107.315,102.489 I²C#.2 105.029,100.203 101.473,100.203 99.568,98.298 99.568,97.917 v1(99.949,97.536)
  Bottom Layer w0.2: v1(99.949,97.536) 100.642,96.843 U4.9
I1D: I²C1.3 I²C#.6 U4.8 | length 31.4
  Top Layer w0.2: I²C1.3 94.107,109.807 94.107,107.823 95.631,106.299 I²C#.6 ; v1(102.362,96.901) 102.87,97.409 104.902,97.409 104.902,96.708 v1(105.09,96.52)
  Inner1 w0.2: v1(105.09,96.52) 105.029,96.581 105.029,98.806 105.918,99.695 106.838,99.695 107.315,100.172 107.315,105.029 I²C#.6
  Bottom Layer w0.2: U4.8 101.864,97.243 102.206,96.901 v1(102.362,96.901)
IOVDD00: C2.1 C7.2 C8.1 C9.1 C10.1 C11.1 C12.1 C13.1 C14.1 C17.2 C21.1 R12.1 U3.8 U4.1 U4.10 U4.22 U4.33 U4.42 U4.44 U4.48 U4.49 U5.1 U5.10 U6.1 U14.5 | length 106.3
  Top Layer w0.2: v1(80.899,91.694) 80.908,91.685 R12.1
  Inner1 w0.2: v1(80.899,91.694) 81.407,92.202 81.407,105.283 v1(82.55,106.426)
  Inner2 w0.2: v1(92.456,89.535) 96.012,89.535 ; v1(93.218,80.391) 95.758,80.391 v1(96.901,79.248) 96.901,88.646 96.012,89.535 ; v1(97.79,90.424) 96.901,89.535 96.012,89.535
  Bottom Layer w0.2: v1(82.55,106.426) 83.692,106.426 C9.1@83.712,106.446 ; C9.1 83.601,106.446 C9.1@83.712,106.446 ; C8.1 92.165,108.204 ; U5.1 91.581,90.41 92.032,89.959 ; U5.10 91.588,92.724 92.716,93.853 93.091,93.853 94.523,92.421 94.494,92.421 92.032,89.959 ; U14.5 91.948,80.391 v1(93.218,80.391) ; v1(92.456,89.535) 92.032,89.959 ; U4.33 94.972,96.443 95.377,96.848 ; U4.42 94.191,100.076 95.725,100.076 ; U4.44 95.508,100.293 95.725,100.076 ; U6.1 96.893,79.256 v1(96.901,79.248) ; v1(97.79,90.424) 97.79,91.313 97.615,91.488 97.615,92.885 97.536,92.964 97.536,93.865 U4.22 97.536,93.921 97.536,94.488 97.282,94.742 96.266,94.742 95.377,95.631 95.377,96.848 ; U3.8 98.049,108.204 ; U4.10 100.407,96.443 99.51,97.34 99.51,98.684 99.873,99.047 99.873,99.843 99.673,100.043 ; U4.1 99.673,100.043 ; C9.1@83.712,106.446 C21.1 C7.2 92.8,106.536 C2.1 92.165,108.204 ; 92.165,108.204 98.049,108.204 ; 95.377,96.848 95.377,99.395 96.058,100.076 ; 95.725,100.076 96.058,100.076 ; 96.058,100.076 96.891,100.076 97.108,100.293 ; 97.108,100.293 U4.48 U4.49 97.508,103.787 97.028,104.267 97.028,104.859 97.508,105.339 97.508,107.664 98.049,108.204 ; 97.108,100.293 97.358,100.043 99.673,100.043
PWM0: PWM#.1 U4.29 | length 21.5
  Top Layer w0.2: v1(93.948,94.11) 106.275,94.11 110.343,90.043 PWM#.1
  Bottom Layer w0.2: v1(93.948,94.11) 94.158,94.32 U4.29
PWM1: PWM#.2 U4.31 | length 23.7
  Top Layer w0.2: v1(92.456,96.012) 93.571,94.897 107.252,94.897 107.76,94.389 107.923,94.389 109.729,92.583 PWM#.2
  Bottom Layer w0.2: v1(92.456,96.012) 92.825,95.643 U4.31
PWM2: PWM#.3 U4.34 | length 28.2
  Top Layer w0.2: v1@90.297,97.39 90.963,97.39 91.598,98.025 94.316,98.025 94.951,97.39 96.573,97.39 98.57,95.394 112.632,95.394 PWM#.3
  Bottom Layer w0.2: v1@90.297,97.39 90.613,97.075 91.393,97.075 91.625,96.843 U4.34
  other v1: 90.297,97.409
SPI0CLK: SPI0.4 U4.4 | length 17.3
  Top Layer w0.2: v1(103.251,98.425) 108.017,98.425 109.706,100.114 109.706,101.082 111.198,102.573 111.198,105.102 SPI0.4
  Bottom Layer w0.2: U4.4 102.267,98.843 102.685,98.425 v1(103.251,98.425)
SPI0CSN: SPI0.3 U4.3 | length 15.9
  Inner2 w0.2: v1(102.616,99.06) 102.616,100.33 104.956,102.67 106.861,102.67 107.315,103.124 107.315,104.267 108.077,105.029 112.141,105.029 SPI0.3
  Bottom Layer w0.2: U4.3 102.433,99.243 v1(102.616,99.06)
SPI0RX: SPI0.2 U4.2 | length 19
  Top Layer w0.2: v1@103.004,96.85 103.963,95.891 107.694,95.891 110.45,98.647 110.45,100.177 111.676,101.404 112.58,101.404 SPI0.2
  Bottom Layer w0.2: U4.2 102.119,99.643 102.125,99.637 102.943,99.637 103.862,98.718 103.862,97.384 103.379,96.901 v1(102.997,96.901)
SPI0TX: SPI0.1 U4.5 | length 12.4
  Top Layer w0.2: v1(102.87,97.917) 108.966,97.917 v1(109.474,98.425)
  Inner1 w0.2: v1(109.474,98.425) 110.236,99.187 SPI0.1
  Bottom Layer w0.2: U4.5 102.235,98.443 102.761,97.917 v1(102.87,97.917)
SWCLK0: R16.2 SWD.1 | length 7.5
  Top Layer w0.2: R16.2 90.297,86.054 90.297,87.122 91.837,85.582 SWD.1@91.837,83.599
SWD0: R17.2 R18.1 SWD.3 | length 23.6
  Top Layer w0.2: SWD.3@93.837,83.599 95.377,85.138 95.377,87.122 97.992,87.122 R17.2@98.119,86.995
  Inner1 w0.2: v1(86.211,79.883) 93.853,79.883 95.377,81.407 v1(95.377,83.693)
  Inner2 w0.2: v1(95.377,83.693) SWD.3@95.377,87.122
  Bottom Layer w0.2: v1(86.211,79.883) R18.1
U0R: U4.12 UART0.3 UART#.5 | length 26.9
  Top Layer w0.2: UART0.3 103.665,83.599 UART#.5
  Inner1 w0.2: v1(102.362,95.885) 102.362,95.504 103.076,94.79 103.076,90.165 103.294,89.947 103.294,89.368 103.076,89.15 103.076,88.852 102.743,88.519 101.092,88.519 100.711,88.138 100.711,86.392 101.237,85.866 101.237,85.852 105.918,85.852 UART#.5
  Bottom Layer w0.2: U4.12 102.12,95.643 v1(102.362,95.885)
U0T: U4.11 UART0.1 UART#.1 | length 19.5
  Top Layer w0.2: UART0.1 100.092,85.106 UART#.1
  Inner1 w0.2: v1(100.203,96.012) 100.584,96.393 102.506,96.393 102.87,96.029 102.87,95.631 103.378,95.123 103.378,90.29 103.596,90.072 103.596,89.243 103.378,89.025 103.378,88.392 UART#.1
  Bottom Layer w0.2: v1(100.203,96.012) 101.854,96.012 101.885,96.043 U4.11
U1R: U4.28 UART1.3 UART#.6 | length 23.8
  Top Layer w0.2: v1(94.869,92.837) 94.869,92.71 95.123,92.456 95.123,91.567 95.217,91.473 95.202,91.442 97.617,89.027 101.219,89.027 101.727,88.519 v1(105.537,88.519) ; UART#.6 110.22,86.63 UART1.3
  Inner1 w0.2: v1(105.537,88.519) 106.045,88.519 UART#.6
  Bottom Layer w0.2: v1(94.869,92.837) 95.108,93.076 U4.28
U1T: U4.27 UART1.1 UART#.2 | length 23.5
  Top Layer w0.2: v1(95.504,92.837) 95.504,91.567 97.663,89.408 101.854,89.408 UART#.2 103.759,91.313 104.775,91.313 105.918,90.17 105.918,88.773 106.426,88.265 107.569,88.265 108.585,87.249 108.585,83.837 UART1.1
  Bottom Layer w0.2: v1(95.504,92.837) 95.504,93.889 U4.27
XIN0: C4.2 U4.20 X1.3 | length 14.4
  Bottom Layer w0.2: U4.20 98.298,93.883 98.298,91.948 98.552,91.694 103.251,91.694 104.775,93.218 104.775,94.107 105.326,94.658 X1.3 106.592,93.159 C4.2
XOUT0: R1.2 U4.21 | length 16.4
  Inner1 w0.2: v1(105.283,93.091) 105.537,93.345 v1(105.537,97.409)
  Bottom Layer w0.2: U4.21 97.917,93.884 97.917,91.694 98.298,91.313 103.505,91.313 v1(105.283,93.091) ; v1(105.537,97.409) 105.537,98.477 R1.2
"": U3.9 U14.1 USB1.4

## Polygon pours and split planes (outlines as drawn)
GND on Top Layer (solid, remove dead copper, pour order 0): 76.2,76.2 123.19,76.2 123.19,117.221 76.2,117.221
GND on Inner1 (solid, remove dead copper, pour order 1): 76.2,76.2 123.19,76.2 123.19,117.221 76.2,117.221
GND on Inner2 (solid, remove dead copper, pour order 2): 76.2,76.2 123.19,76.2 123.19,117.221 76.2,117.221
GND on Bottom Layer (solid, remove dead copper, pour order 3): 76.2,76.2 123.19,76.2 123.19,117.221 76.2,117.221

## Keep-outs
Board Outline Layer:
  lines w0.254 net "": 78.74,79.681 ccw(c79.74,79.681) 79.74,78.681 119.74,78.681 ccw(c119.74,79.681) 120.74,79.681 120.74,113.681 ccw(c119.74,113.681) 119.74,114.681 79.74,114.681 ccw(c79.74,113.681) 78.74,113.681 78.74,79.681

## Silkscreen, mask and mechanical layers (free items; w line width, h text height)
Top Silkscreen Layer:
  text "JLCJLCJLCJLC" at 82.3,110.287 h0.52
  text "USB to" at 91.709,100.643 h1.7
  text "I²Cx2,SPIx1, /  UARTx2,SWDx1, /  PWMx3,ADCx3" at 91.679,97.616 h0.86
  text "Protocol converter" at 91.738,95.713 h1.13
  text "version 0 build 0" at 91.725,94.518 h0.85
  text "Design by wangyupu /  Powered by RP2040" at 91.679,92.573 h0.86
Mechanical Layer:
  circle w0.025 net "": c81.24,112.181 r1.1
  circle w0.025 net "": c81.24,81.181 r1.1
  circle w0.025 net "": c118.24,112.181 r1.1
  circle w0.025 net "": c118.24,81.181 r1.1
